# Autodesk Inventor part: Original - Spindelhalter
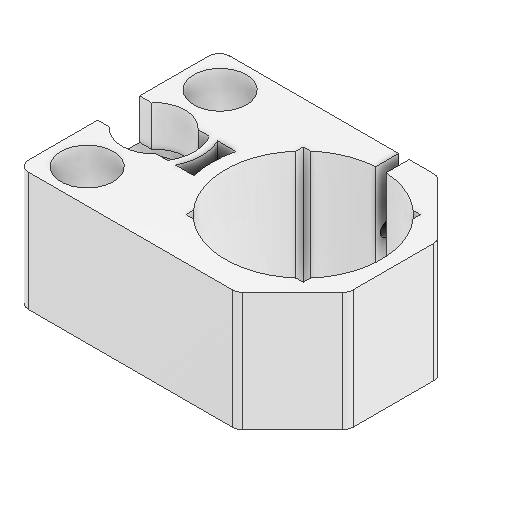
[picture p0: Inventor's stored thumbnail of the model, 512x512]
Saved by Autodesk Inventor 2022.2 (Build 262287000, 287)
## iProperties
Created: 2024-09
Part Number: Original - Spindelhalter
Material: Generico
Document SubType Name: Modeling
Designer: 18907419
Density: 1 g/cm^3
Appearance: Default
Author: 18907419
Revision Number: ANY
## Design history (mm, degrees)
feature "Schnitt-Linear austragen9"
node "Solido1"
